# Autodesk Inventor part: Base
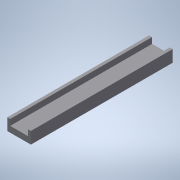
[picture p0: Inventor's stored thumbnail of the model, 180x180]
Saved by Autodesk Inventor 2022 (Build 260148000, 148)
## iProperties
Created: 2014-03
Part Number: Base
Material: Generic
Document SubType Name: Modeling
Designer: John
Density: 1 g/cm^3
Appearance: Default
Author: John
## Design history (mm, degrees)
sketch "Sketch1"
  geometry: L1 (12.7, 76.2)-(-12.7, 76.2); L2 (-12.7, 76.2)-(-12.7, -76.2); L3 (-12.7, -76.2)-(12.7, -76.2); L4 (12.7, -76.2)-(12.7, 76.2); L5 (12.7, 76.2)-(-12.7, -76.2); L6 (-12.7, 76.2)-(12.7, -76.2); 1 further point
  constraints: 12 end point, 2 midpoint, 2 parallel, 1 horizontal, 1 perpendicular
  dimensions: "d0" = 25.4 distance of L3.end L2.end; "d1" = 152.4 distance of L2.end L1.end
extrude "Extrusion1" new body sketch "Sketch1" distance "d2" = 12.7; taper "d3" = 0 deg
sketch "Sketch2"
  geometry: L1 (0, 0)-(25.4, 0) reference; L2 (25.4, 0)-(25.4, 12.7) reference; L3 (0, 12.7)-(25.4, 12.7) reference; L4 (0, 0)-(0, 12.7) reference; L5 (3.175, 12.7)-(22.225, 12.7); L6 (22.225, 12.7)-(22.225, 6.35); L7 (22.225, 6.35)-(3.175, 6.35); L8 (3.175, 6.35)-(3.175, 12.7); 1 further point
  constraints: 8 end point, 2 parallel, 1 horizontal, 1 perpendicular, 1 point on line
  dimensions: "d4" = 3.175 distance between parallel lines of L2 L6; "d5" = 6.35 distance between parallel lines of L1 L7; "d6" = 3.175 distance between parallel lines of L4 L8 (= d4)
extrude "Extrusion2" cut sketch "Sketch2" extent not by distance; stored distance "d7" = 12.7; taper "d8" = 0 deg
body "Solid1"
